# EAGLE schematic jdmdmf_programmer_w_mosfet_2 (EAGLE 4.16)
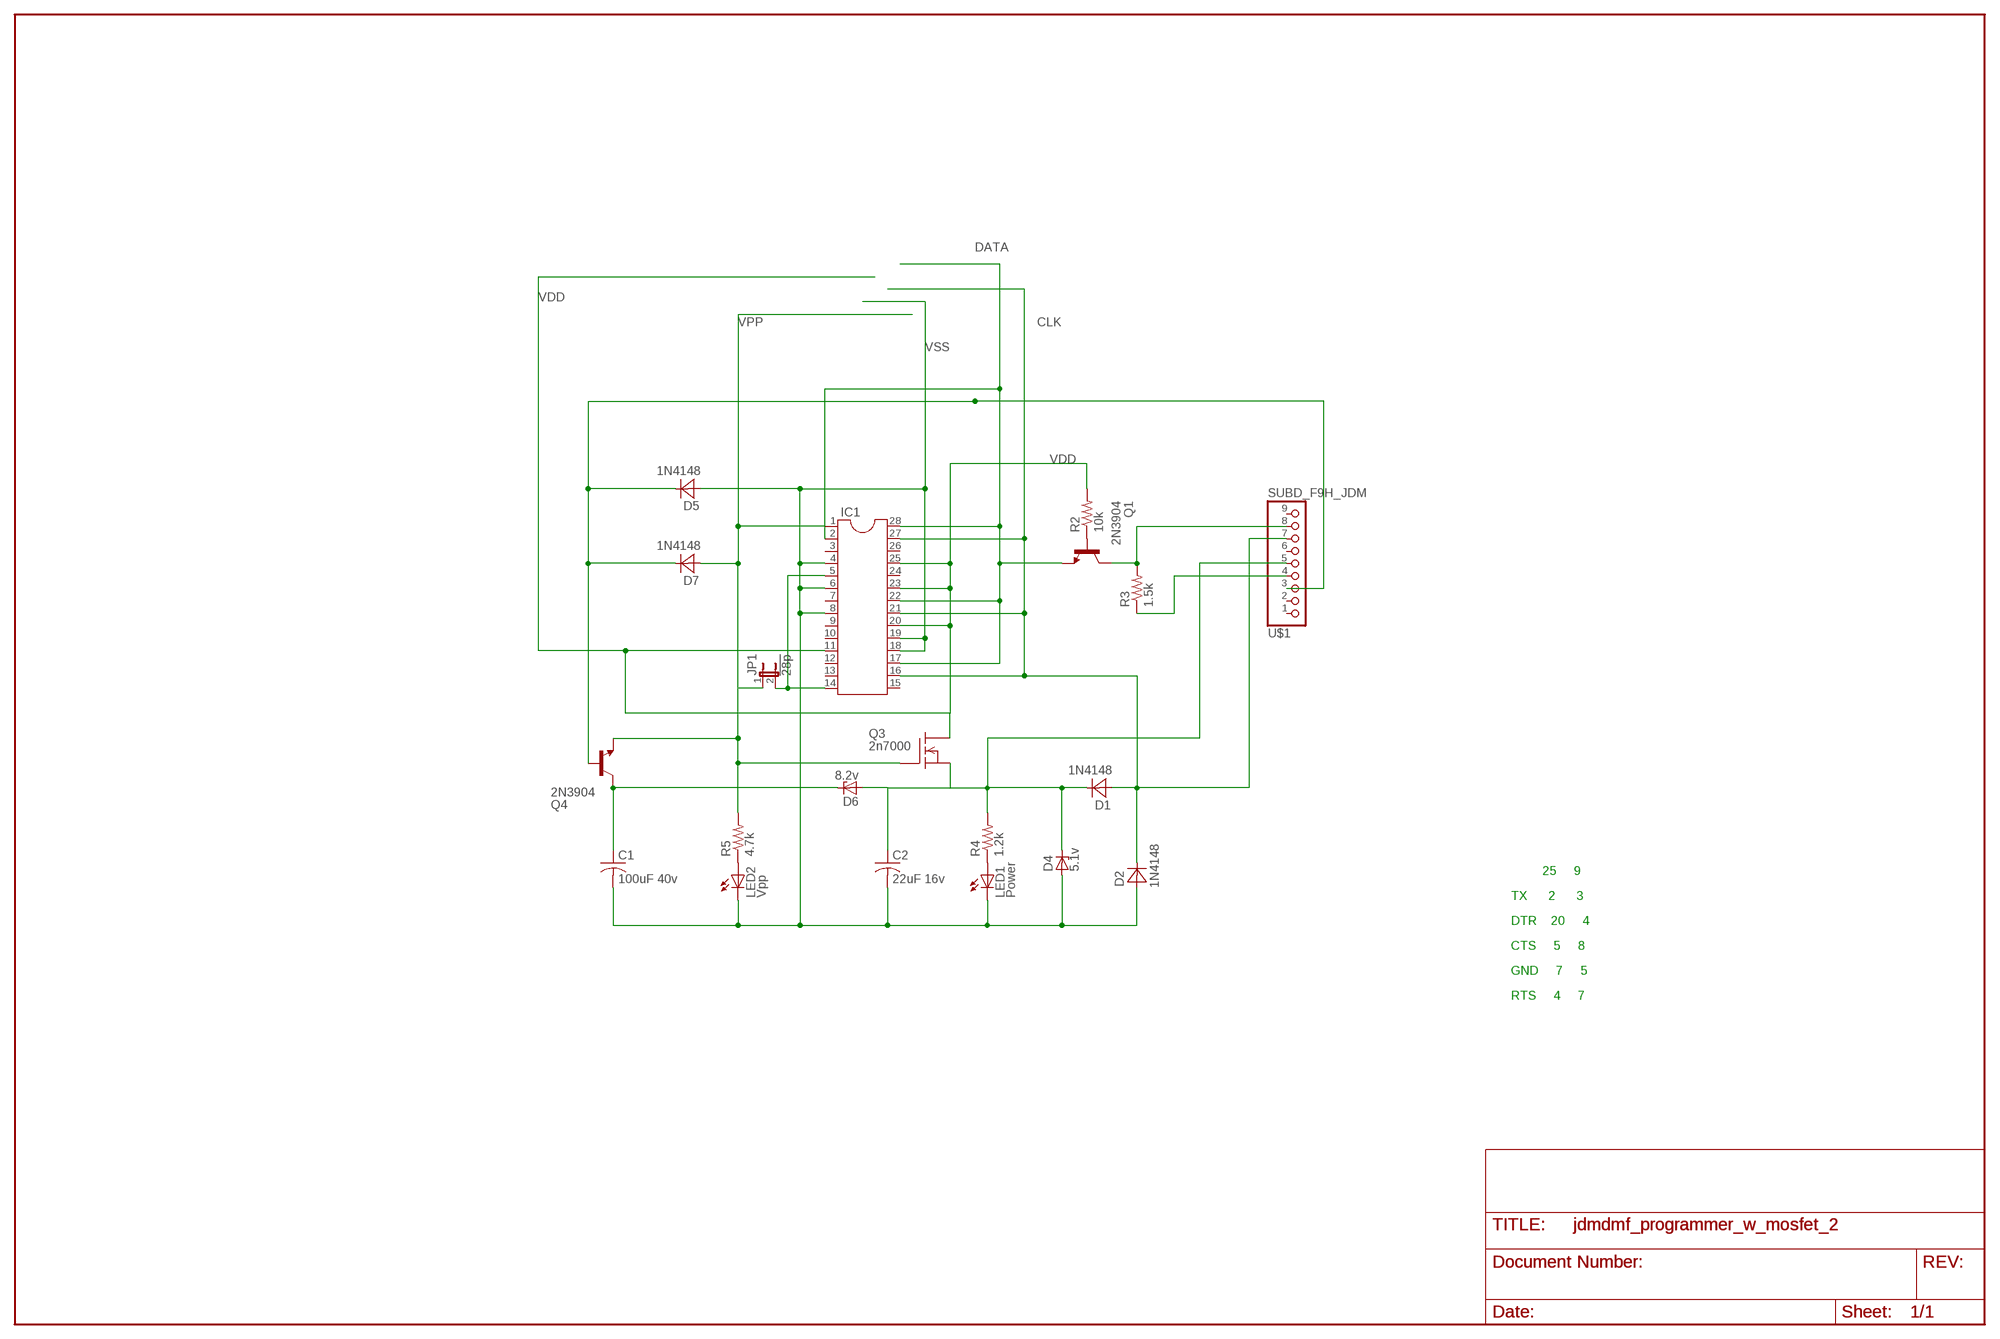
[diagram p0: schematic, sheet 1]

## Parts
C1  100uF 40v  CPOL-US  [CPOL-USE5-6]
C2  22uF 16v  CPOL-US  [CPOL-USE5-6]
D1  1N4148  DIODE_DO35-10  [DIODE_DO35-10]
D2  1N4148  DIODE_DO35-10  [DIODE_DO35-10]
D4  5.1v  ZENER-DIODEDO35Z10  [DO35Z10]
D5  1N4148  DIODE_DO35-10  [DIODE_DO35-10]
D6  8.2v  ZENER-DIODEDO35Z10  [DO35Z10]
D7  1N4148  DIODE_DO35-10  [DIODE_DO35-10]
IC1  DIL28  [DIL28-6]
JP1  !28p  JP1E  [JP1]
LED1  Power  LED  [LED5MM]
LED2  Vpp  LED  [LED5MM]
Q1  2N3904  NPN_TO92_BP  [NPN_TO92_BP]
Q3  2n7000  MOSFET-N  [TO_237]
Q4  2N3904  NPN_TO92_BP  [NPN_TO92_BP]
R2  10k  R-US  [R_US_0204/7]
R3  1.5k  R-US  [R_US_0204/7]
R4  1.2k  R-US  [R_US_0204/7]
R5  4.7k  R-US  [R_US_0204/7]
U$1  SUBD_F9H_JDM  [SUBD_F9H]

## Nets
2N3904: C1.+ D6.C Q4.1(C)
CLK: D1.A D2.C IC1.16 IC1.21 IC1.27 U$1.7
DATA: IC1.2 IC1.17 IC1.22 IC1.28 Q1.3(E)
N$1: Q1.2(B) R2.1
N$2: LED1.A R4.1
N$3: LED2.A R5.1
N$4: R3.1 U$1.4
N$5: Q1.1(C) R3.2 U$1.8
N$6: D5.C D7.C Q4.2(B) U$1.3
N$7: IC1.5 IC1.14 JP1.2
Q3: C2.+ D1.C D4.C D6.A Q3.3(S1) R4.2 U$1.5
VDD: IC1.11 IC1.20 IC1.23 IC1.25 Q3.1(D2) R2.2
VPP: D7.A IC1.1 JP1.1 Q3.2(G1) Q4.3(E) R5.2
VSS: C1.- C2.- D2.A D4.A D5.A IC1.4 IC1.6 IC1.8 IC1.18 IC1.19 LED1.K(C) LED2.K(C)
Unconnected: IC1.3 IC1.7 IC1.9 IC1.10 IC1.12 IC1.13 IC1.15 IC1.24 IC1.26 U$1.1 U$1.2 U$1.6 U$1.9

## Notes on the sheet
- 25     9
- TX      2      3
- DTR    20     4
- CTS     5     8
- GND     7     5
- RTS     4     7

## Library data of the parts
C1 C2 = 1dmf:CPOL-US
D1 D2 D5 D7 = 1dmf:DIODE_DO35-10
D4 D6 = diode:ZENER-DIODE: Z-Diode
IC1 = ic-package:DIL28: Dual In Line
JP1 = jumper:JP1E: JUMPER
LED1 LED2 = 1dmf:LED
Q1 Q4 = 1dmf:NPN_TO92_BP
Q3 = 1dmf:MOSFET-N
R2-R5 = 1dmf:R-US
U$1 = 1dmf:SUBD_F9H_JDM

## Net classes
0 default: width 0.559 mm
1 power: width 0.559 mm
